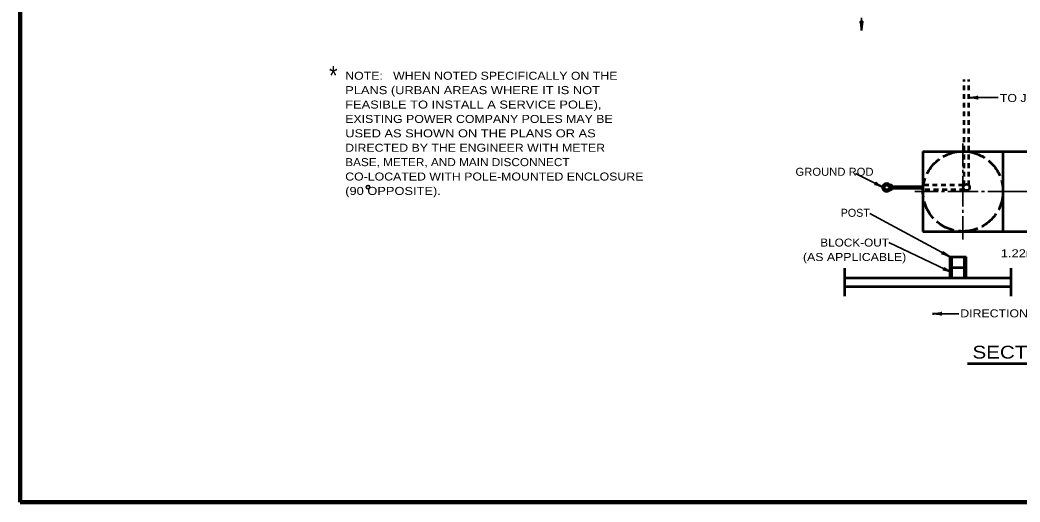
# Model space of a CAD drawing. Extents: x -111 to 744, y -77 to 467.
# Drawn here: x -54 to 320.8, y -65.8 to 115 of the extents above; entities that cross this region are included whole.
import ezdxf
from ezdxf.enums import TextEntityAlignment as Align

# ---------------------------------------------------------------- set-up
doc = ezdxf.new("R2010")
doc.units = 0
doc.header["$LTSCALE"] = 1.2
doc.linetypes.add('LONG_DASHED', pattern=[7.5, 6, -1.5])
doc.linetypes.add('SHORT_DASHED', pattern=[2.7, 1.5, -1.2])
doc.layers.add('1', color=7, linetype='Continuous', lineweight=53)

msp = doc.modelspace()

# ---------------------------------------------------------------- linework, layer by layer
at = {"layer": '1', "lineweight": 35}
for p, q in [((261.439, 115.831), (261.439, 111.031)), ((301.676, 85.86), (312.688, 85.86)), ((299.465, 68.675), (299.465, 65.675)), ((299.465, 65.675), (299.465, 59.975)), ((269.656, 52.128), (259.208, 57.337)), ((299.465, 58.775), (299.465, 57.575)), ((299.465, 56.375), (299.465, 50.675)), ((281.465, 50.675), (284.465, 50.675)), ((284.465, 50.675), (290.165, 50.675)), ((291.365, 50.675), (292.565, 50.675)), ((299.465, 50.675), (305.165, 50.675)), ((306.365, 50.675), (307.565, 50.675)), ((308.765, 50.675), (314.465, 50.675)), ((314.465, 50.675), (324.065, 50.675)), ((294.665, 26.075), (264.499, 42.421)), ((299.465, 43.775), (299.465, 42.575)), ((299.465, 41.375), (299.465, 35.675)), ((299.465, 35.675), (299.465, 32.675)), ((295.265, 20.211), (271.723, 31.445)), ((297.932, 4.779), (288.058, 4.779))]:
    msp.add_line(p, q, dxfattribs=at)
at = {"layer": '1', "linetype": 'SHORT_DASHED'}
for p, q in [((299.876, 52.964), (299.876, 92.675)), ((301.676, 52.964), (301.676, 92.675)), ((299.576, 53.07), (284.465, 53.07)), ((299.983, 51.27), (284.465, 51.27))]:
    msp.add_line(p, q, dxfattribs=at)
at = {"layer": '1'}
for p, q in [((284.465, 65.675), (324.065, 65.675)), ((284.465, 65.675), (284.465, 35.675)), ((314.465, 65.675), (314.465, 35.675)), ((284.465, 35.675), (324.065, 35.675)), ((295.265, 18.275), (295.265, 26.075)), ((300.065, 18.275), (300.065, 26.075)), ((300.665, 18.275), (300.665, 26.075)), ((255.065, 21.875), (255.065, 11.375)), ((295.265, 22.175), (300.065, 22.175)), ((317.465, 21.875), (317.465, 11.375)), ((255.065, 18.275), (317.465, 18.275)), ((255.065, 14.975), (317.465, 14.975)), ((301.229, -13.857), (359.176, -13.857))]:
    msp.add_line(p, q, dxfattribs=at)
at = {"layer": '1', "lineweight": 90}
msp.add_line((284.465, 52.17), (272.465, 52.17), dxfattribs=at)
at = {"layer": '1', "lineweight": 158}
msp.add_line((737.728, -65.835), (-53.872, -65.835), dxfattribs=at)
msp.add_lwpolyline([(737.728, 460.265), (-53.972, 460.165), (-53.872, -65.835)], dxfattribs=at)
at = {"layer": '1', "lineweight": 90}
msp.add_lwpolyline([(271.865, 52.77), (272.465, 52.77), (272.465, 51.57), (271.865, 51.57), (271.907, 51.57)], dxfattribs=at)
at = {"layer": '1', "lineweight": 35}
msp.add_lwpolyline([(293.765, 50.675), (299.465, 50.675), (299.465, 44.975)], dxfattribs=at)
at = {"layer": '1'}
msp.add_lwpolyline([(294.665, 18.275), (294.665, 26.075), (300.665, 26.075)], dxfattribs=at)
at = {"layer": '1', "linetype": 'LONG_DASHED'}
msp.add_circle((299.465, 50.675), 15, dxfattribs=at)
at = {"layer": '1', "lineweight": 35}
msp.add_circle((76.485, 52.271), 0.671, dxfattribs=at)
at = {"layer": '1'}
msp.add_circle((300.776, 52.17), 1.2, dxfattribs=at)
at = {"layer": '1', "lineweight": 90}
msp.add_arc((270.856, 52.15), 1.2, 31.09219, 331.0803, dxfattribs=at)
at = {"layer": '1', "lineweight": 40}
for centre, major_axis, ratio, start_param, end_param in [((261.108, 112.34), (0.187, -2.143), 0.122415, 0.8963533, 3.1415927), ((261.693, 112.375), (-0.211, -2.108), 0.07063, 3.1407148, 5.41811), ((302.986, 86.191), (-2.143, -0.187), 0.122415, 0.8963533, 3.1415927), ((302.986, 86.191), (-2.143, -0.187), 0.122415, 0.8963533, 3.1415927), ((303.021, 85.606), (-2.108, 0.211), 0.07063, 3.1407148, 5.41811), ((303.021, 85.606), (-2.108, 0.211), 0.07063, 3.1407148, 5.41811), ((268.337, 52.415), (2.001, -0.788), 0.122415, 0.8963533, 3.1415927), ((268.337, 52.415), (2.001, -0.788), 0.122415, 0.8963533, 3.1415927), ((268.566, 52.955), (-1.792, 1.129), 0.07063, 6.2823074, 8.5597026), ((268.566, 52.955), (-1.792, 1.129), 0.07063, 6.2823074, 8.5597026), ((293.356, 26.408), (1.973, -0.856), 0.122415, 0.8963533, 3.1415927), ((293.356, 26.408), (1.973, -0.856), 0.122415, 0.8963533, 3.1415927), ((293.604, 26.939), (-1.753, 1.189), 0.07063, 6.2823074, 8.5597026), ((293.604, 26.939), (-1.753, 1.189), 0.07063, 6.2823074, 8.5597026), ((293.94, 20.475), (2.015, -0.754), 0.122415, 0.8963533, 3.1415927), ((294.161, 21.019), (1.811, -1.098), 0.07063, 3.1407148, 5.41811), ((289.402, 4.525), (-2.108, 0.211), 0.07063, 3.1407148, 5.41811), ((289.402, 4.525), (-2.108, 0.211), 0.07063, 3.1407148, 5.41811), ((289.367, 5.111), (-2.143, -0.187), 0.122415, 0.8963533, 3.1415927), ((289.367, 5.111), (-2.143, -0.187), 0.122415, 0.8963533, 3.1415927)]:
    msp.add_ellipse(centre, major_axis=major_axis, ratio=ratio, start_param=start_param, end_param=end_param, dxfattribs=at)

# ---------------------------------------------------------------- texts
at = {"layer": '1'}
for s, height, width, p in [('*', 7.2, 0.85, (61.881, 90.53)), ('NOTE:   WHEN NOTED SPECIFICALLY ON THE', 3, 1.15, (67.928, 92.549)), ('PLANS (URBAN AREAS WHERE IT IS NOT', 3, 1.2, (67.928, 87.149)), ('FEASIBLE TO INSTALL A SERVICE POLE),', 3, 1.2, (67.928, 81.749)), ('EXISTING POWER COMPANY POLES MAY BE', 3, 1.15, (67.928, 76.349)), ('USED AS SHOWN ON THE PLANS OR AS', 3, 1.2, (67.928, 70.949)), ('DIRECTED BY THE ENGINEER WITH METER', 3, 1.15, (67.928, 65.549)), ('BASE, METER, AND MAIN DISCONNECT', 3, 1.1, (67.928, 60.149)), ('CO-LOCATED WITH POLE-MOUNTED ENCLOSURE', 3, 1.15, (67.928, 54.749)), ('(90 OPPOSITE).', 3, 1.2, (67.928, 49.349))]:
    msp.add_text(s, height=height, dxfattribs=dict(at, width=width)).set_placement(p)
for s, height, width, p in [('TO JUNCTION BOX', 3, 1.15, (334.321, 84.204)), ('GROUND ROD', 3, 1.05, (251.33, 56.531)), ('BLOCK-OUT', 3, 1.1, (258.852, 29.97)), ('(AS APPLICABLE)', 3, 1.15, (258.852, 24.57)), ('1.22m MIN.', 3, 1.2, (326.103, 25.959)), ('DIRECTION OF TRAFFIC', 3, 1.15, (325.374, 3.423)), ('SECTION "B-B"', 4.8, 1.2, (330.39, -12.032))]:
    msp.add_text(s, height=height, dxfattribs=dict(at, width=width)).set_placement(p, align=Align.CENTER)
msp.add_text('POST', height=3, dxfattribs=at).set_placement((259.103, 41.148), align=Align.CENTER)

doc.saveas('drawing.dxf')
